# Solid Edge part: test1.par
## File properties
Author: CADCIM
Template: Normal.par
Last saved by: CADCIM
Revision: 1
Application: Solid Edge
Density: 0 kg/mm^3
Accuracy: 0.99
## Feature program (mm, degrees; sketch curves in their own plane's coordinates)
sketch for "unnamed Protrusion 1" #1 plane through (0, 0, 0) normal (0, 0, 1) x-axis (1, 0, 0)
  line (-47.52, 0) -> (-47.52, 46.944)
  line (-47.52, 46.944) -> (47.52, 46.944)
  line (47.52, 46.944) -> (47.52, 0)
  line (47.52, 0) -> (-47.52, 0)
sketch for "unnamed Protrusion 1" #2 plane through (0, 0, 0) normal (0, 0, 1) x-axis (1, 0, 0)
  circle centre (-33.4173, 33.1293) radius 7.1111
sketch for "unnamed Protrusion 1" #3 plane through (0, 0, 0) normal (0, 0, 1) x-axis (1, 0, 0)
  circle centre (0, 13.2015) radius 7.2161
sketch for "unnamed Protrusion 1" #4 plane through (0, 0, 0) normal (0, 0, 1) x-axis (1, 0, 0)
  circle centre (36.4831, 33.1293) radius 6.1622
extrude "unnamed Protrusion 1" add finite 6.35 along +normal
sketch for "ExtrudedProtrusion_2" #1 plane through (0, 23.472, 6.35) normal (0, 0, 1) x-axis (0, 1, 0)
sketch for "ExtrudedProtrusion_2" #2 plane through (0, 23.472, 6.35) normal (0, 0, 1) x-axis (0, 1, 0)
sketch for "ExtrudedProtrusion_2" #3 plane through (0, 23.472, 6.35) normal (0, 0, 1) x-axis (0, 1, 0)
  circle centre (-10.2705, 0) radius 7.2161
extrude "ExtrudedProtrusion_2" add finite 28.575 along -normal
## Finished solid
Body 1: solid body, 12 faces, 18 edges, 8 vertices.
  Faces by surface: plane 9, cylinder 3
  Edges by curve: line 12, circle 6
Bounding box of the edges (mm): 95.040 x 46.944 x 28.575, from (-47.52, 0, -22.225) to (47.52, 46.944, 6.35).
Cylindrical faces by radius (mm): R6.1622 x1, R7.1111 x1, R7.2161 x1
Planar faces by outward normal: +x 1, +y 1, +z 1, -x 1, -y 1, -z 4
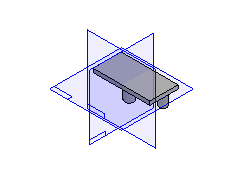
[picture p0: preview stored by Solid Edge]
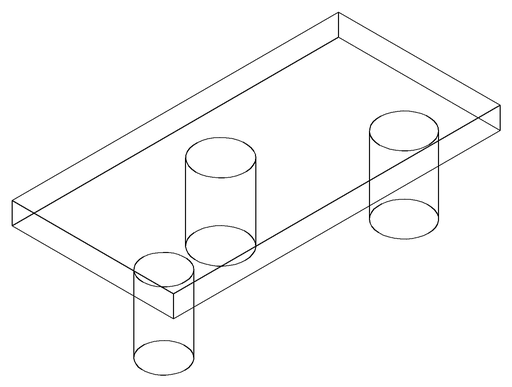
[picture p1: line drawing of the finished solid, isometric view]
